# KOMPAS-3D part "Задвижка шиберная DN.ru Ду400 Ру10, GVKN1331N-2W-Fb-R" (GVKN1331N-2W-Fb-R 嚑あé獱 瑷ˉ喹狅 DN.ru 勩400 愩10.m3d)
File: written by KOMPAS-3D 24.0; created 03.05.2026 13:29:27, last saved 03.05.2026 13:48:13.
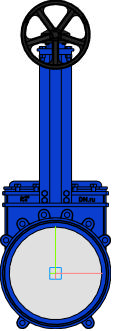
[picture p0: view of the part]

Document properties: Автор: DN.ru; Полное имя файла: C:\Работа\GVKN1331N-2W-Fb-R Задвижка шиберная DN.ru Ду400-600 Ру10\DN400\GVKN1331N-2W-Fb-R Задвижка шиберная DN.ru Ду400 Ру10.m3d

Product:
- Part/product: Задвижка шиберная DN.ru Ду400 Ру10  | designation GVKN1331N-2W-Fb-R
    Масса: 122
    Раздел спецификации: Прочие изделия
    Примечание: D040-07840

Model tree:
1. Операция без истории:1

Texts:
  GVKN1331N-2W-Fb-R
